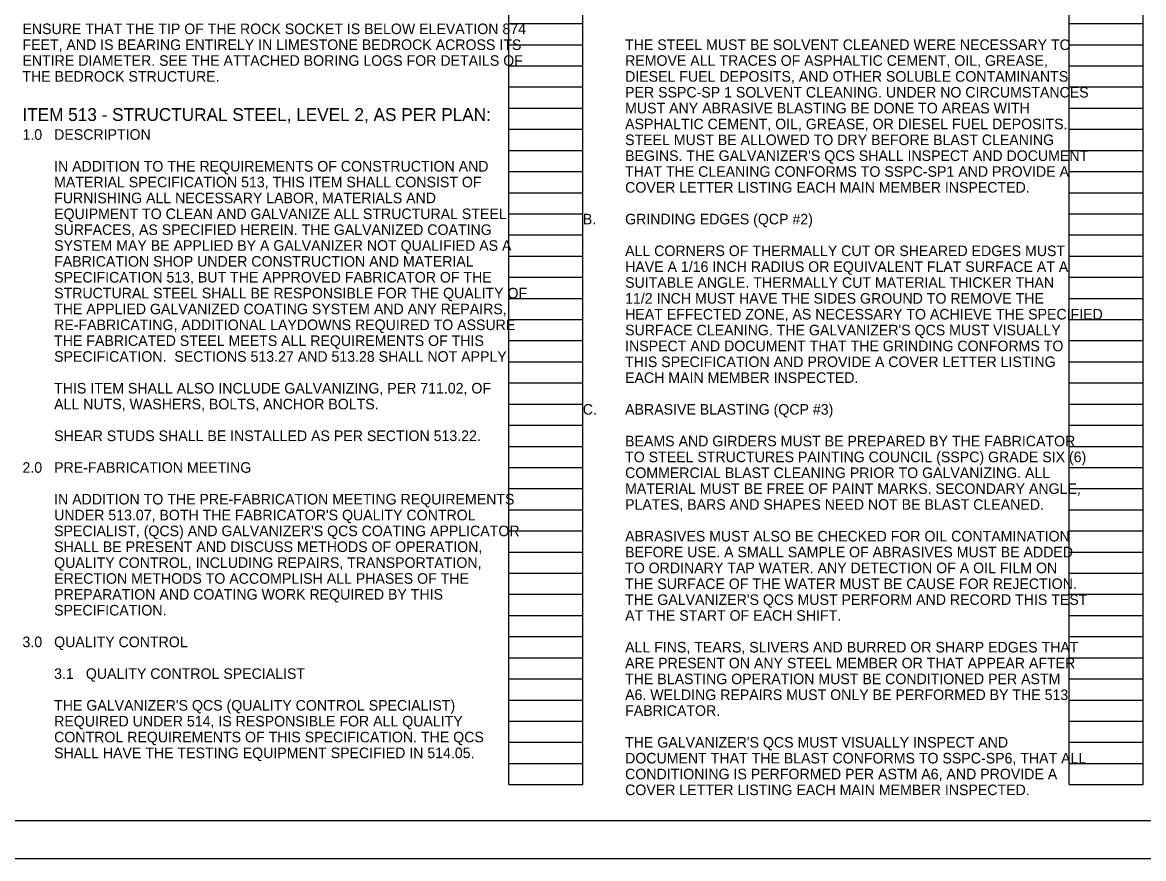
# Model space of a CAD drawing. Extents: x 0 to 45.3, y 0 to 22.
# Drawn here: x 9.82 to 24.66, y 0 to 11.07 of the extents above; entities that cross this region are included whole.
import ezdxf

# ---------------------------------------------------------------- set-up
doc = ezdxf.new("R2010")
doc.units = 0
for name, color, linetype in [('BR_P_Gen_Text', 7, 'Continuous'), ('SH_Border', 7, 'Continuous'), ('SH_Cut_Line', 7, 'Continuous'), ('SH_Data', 7, 'Continuous'), ('SH_Text', 7, 'Continuous')]:
    doc.layers.add(name, color=color, linetype=linetype)

msp = doc.modelspace()

# ---------------------------------------------------------------- linework, layer by layer
at = {"layer": 'SH_Border'}
msp.add_lwpolyline([(1.5, 21.5), (33.5, 21.5), (33.5, 0.5), (1.5, 0.5)], close=True, dxfattribs=at)
at = {"layer": 'SH_Cut_Line'}
msp.add_lwpolyline([(0, 0), (34, 0), (34, 22), (0, 22)], close=True, dxfattribs=at)
at = {"layer": 'SH_Data'}
for p, q in [((16.26, 0.98), (16.26, 21.14)), ((17.24, 0.98), (17.24, 21.14)), ((23.68, 0.98), (23.68, 21.14)), ((24.66, 0.98), (24.66, 21.14)), ((16.26, 11.06), (17.24, 11.06)), ((23.68, 11.06), (24.66, 11.06)), ((16.26, 10.78), (17.24, 10.78)), ((23.68, 10.78), (24.66, 10.78)), ((16.26, 10.5), (17.24, 10.5)), ((23.68, 10.5), (24.66, 10.5)), ((16.26, 10.22), (17.24, 10.22)), ((23.68, 10.22), (24.66, 10.22)), ((16.26, 9.94), (17.24, 9.94)), ((23.68, 9.94), (24.66, 9.94)), ((16.26, 9.66), (17.24, 9.66)), ((23.68, 9.66), (24.66, 9.66)), ((16.26, 9.38), (17.24, 9.38)), ((23.68, 9.38), (24.66, 9.38)), ((16.26, 9.1), (17.24, 9.1)), ((23.68, 9.1), (24.66, 9.1)), ((16.26, 8.82), (17.24, 8.82)), ((23.68, 8.82), (24.66, 8.82)), ((16.26, 8.54), (17.24, 8.54)), ((23.68, 8.54), (24.66, 8.54)), ((16.26, 8.26), (17.24, 8.26)), ((23.68, 8.26), (24.66, 8.26)), ((16.26, 7.98), (17.24, 7.98)), ((23.68, 7.98), (24.66, 7.98)), ((16.26, 7.7), (17.24, 7.7)), ((23.68, 7.7), (24.66, 7.7)), ((16.26, 7.42), (17.24, 7.42)), ((23.68, 7.42), (24.66, 7.42)), ((16.26, 7.14), (17.24, 7.14)), ((23.68, 7.14), (24.66, 7.14)), ((16.26, 6.86), (17.24, 6.86)), ((23.68, 6.86), (24.66, 6.86)), ((16.26, 6.58), (17.24, 6.58)), ((23.68, 6.58), (24.66, 6.58)), ((16.26, 6.3), (17.24, 6.3)), ((23.68, 6.3), (24.66, 6.3)), ((16.26, 6.02), (17.24, 6.02)), ((23.68, 6.02), (24.66, 6.02)), ((16.26, 5.74), (17.24, 5.74)), ((23.68, 5.74), (24.66, 5.74)), ((16.26, 5.46), (17.24, 5.46)), ((23.68, 5.46), (24.66, 5.46)), ((16.26, 5.18), (17.24, 5.18)), ((23.68, 5.18), (24.66, 5.18)), ((16.26, 4.9), (17.24, 4.9)), ((23.68, 4.9), (24.66, 4.9)), ((16.26, 4.62), (17.24, 4.62)), ((23.68, 4.62), (24.66, 4.62)), ((16.26, 4.34), (17.24, 4.34)), ((23.68, 4.34), (24.66, 4.34)), ((16.26, 4.06), (17.24, 4.06)), ((23.68, 4.06), (24.66, 4.06)), ((16.26, 3.78), (17.24, 3.78)), ((23.68, 3.78), (24.66, 3.78)), ((16.26, 3.5), (17.24, 3.5)), ((23.68, 3.5), (24.66, 3.5)), ((16.26, 3.22), (17.24, 3.22)), ((23.68, 3.22), (24.66, 3.22)), ((16.26, 2.94), (17.24, 2.94)), ((23.68, 2.94), (24.66, 2.94)), ((16.26, 2.66), (17.24, 2.66)), ((23.68, 2.66), (24.66, 2.66)), ((16.26, 2.38), (17.24, 2.38)), ((23.68, 2.38), (24.66, 2.38)), ((16.26, 2.1), (17.24, 2.1)), ((23.68, 2.1), (24.66, 2.1)), ((16.26, 1.82), (17.24, 1.82)), ((23.68, 1.82), (24.66, 1.82)), ((16.26, 1.54), (17.24, 1.54)), ((23.68, 1.54), (24.66, 1.54)), ((16.26, 1.26), (17.24, 1.26)), ((23.68, 1.26), (24.66, 1.26)), ((16.26, 0.98), (17.24, 0.98)), ((23.68, 0.98), (24.66, 0.98))]:
    msp.add_line(p, q, dxfattribs=at)

# ---------------------------------------------------------------- texts
at = {"layer": 'BR_P_Gen_Text'}
for s, height, p in [('THE STEEL MUST BE SOLVENT CLEANED WERE NECESSARY TO ', 0.14, (17.8, 10.71)), ('REMOVE ALL TRACES OF ASPHALTIC CEMENT, OIL, GREASE, ', 0.14, (17.8, 10.5)), ('DIESEL FUEL DEPOSITS, AND OTHER SOLUBLE CONTAMINANTS ', 0.14, (17.8, 10.29)), ('PER SSPC-SP 1 SOLVENT CLEANING. UNDER NO CIRCUMSTANCES ', 0.14, (17.8, 10.08)), ('MUST ANY ABRASIVE BLASTING BE DONE TO AREAS WITH ', 0.14, (17.8, 9.87)), ('ITEM 513 - STRUCTURAL STEEL, LEVEL 2, AS PER PLAN:', 0.17, (9.82, 9.77)), ('ASPHALTIC CEMENT, OIL, GREASE, OR DIESEL FUEL DEPOSITS. ', 0.14, (17.8, 9.66)), ('1.0', 0.14, (9.821, 9.52)), ('DESCRIPTION', 0.14, (10.24, 9.52)), ('STEEL MUST BE ALLOWED TO DRY BEFORE BLAST CLEANING ', 0.14, (17.8, 9.45)), ("BEGINS. THE GALVANIZER'S QCS SHALL INSPECT AND DOCUMENT ", 0.14, (17.8, 9.24)), ('IN ADDITION TO THE REQUIREMENTS OF CONSTRUCTION AND ', 0.14, (10.24, 9.1)), ('THAT THE CLEANING CONFORMS TO SSPC-SP1 AND PROVIDE A ', 0.14, (17.8, 9.03)), ('MATERIAL SPECIFICATION 513, THIS ITEM SHALL CONSIST OF ', 0.14, (10.24, 8.89)), ('COVER LETTER LISTING EACH MAIN MEMBER INSPECTED.', 0.14, (17.8, 8.82)), ('FURNISHING ALL NECESSARY LABOR, MATERIALS AND ', 0.14, (10.24, 8.68)), ('EQUIPMENT TO CLEAN AND GALVANIZE ALL STRUCTURAL STEEL ', 0.14, (10.24, 8.47)), ('B.', 0.14, (17.24, 8.4)), ('GRINDING EDGES (QCP #2)', 0.14, (17.8, 8.4)), ('SURFACES, AS SPECIFIED HEREIN. THE GALVANIZED COATING ', 0.14, (10.24, 8.26)), ('SYSTEM MAY BE APPLIED BY A GALVANIZER NOT QUALIFIED AS A ', 0.14, (10.24, 8.05)), ('ALL CORNERS OF THERMALLY CUT OR SHEARED EDGES MUST ', 0.14, (17.8, 7.98)), ('FABRICATION SHOP UNDER CONSTRUCTION AND MATERIAL ', 0.14, (10.24, 7.84)), ('HAVE A 1/16 INCH RADIUS OR EQUIVALENT FLAT SURFACE AT A ', 0.14, (17.8, 7.77)), ('SPECIFICATION 513, BUT THE APPROVED FABRICATOR OF THE ', 0.14, (10.24, 7.63)), ('SUITABLE ANGLE. THERMALLY CUT MATERIAL THICKER THAN ', 0.14, (17.8, 7.56)), ('STRUCTURAL STEEL SHALL BE RESPONSIBLE FOR THE QUALITY OF ', 0.14, (10.24, 7.42)), ('11/2 INCH MUST HAVE THE SIDES GROUND TO REMOVE THE ', 0.14, (17.8, 7.35)), ('THE APPLIED GALVANIZED COATING SYSTEM AND ANY REPAIRS, ', 0.14, (10.24, 7.21)), ('HEAT EFFECTED ZONE, AS NECESSARY TO ACHIEVE THE SPECIFIED ', 0.14, (17.8, 7.14)), ('RE-FABRICATING, ADDITIONAL LAYDOWNS REQUIRED TO ASSURE ', 0.14, (10.24, 7)), ("SURFACE CLEANING. THE GALVANIZER'S QCS MUST VISUALLY ", 0.14, (17.8, 6.93)), ('THE FABRICATED STEEL MEETS ALL REQUIREMENTS OF THIS ', 0.14, (10.24, 6.79)), ('INSPECT AND DOCUMENT THAT THE GRINDING CONFORMS TO ', 0.14, (17.8, 6.72)), ('SPECIFICATION.  SECTIONS 513.27 AND 513.28 SHALL NOT APPLY.', 0.14, (10.24, 6.58)), ('THIS SPECIFICATION AND PROVIDE A COVER LETTER LISTING ', 0.14, (17.8, 6.51)), ('EACH MAIN MEMBER INSPECTED.', 0.14, (17.8, 6.3)), ('THIS ITEM SHALL ALSO INCLUDE GALVANIZING, PER 711.02, OF ', 0.14, (10.24, 6.16)), ('ALL NUTS, WASHERS, BOLTS, ANCHOR BOLTS.', 0.14, (10.24, 5.95)), ('C.', 0.14, (17.24, 5.88)), ('ABRASIVE BLASTING (QCP #3)', 0.14, (17.8, 5.88)), ('SHEAR STUDS SHALL BE INSTALLED AS PER SECTION 513.22. ', 0.14, (10.24, 5.53)), ('BEAMS AND GIRDERS MUST BE PREPARED BY THE FABRICATOR ', 0.14, (17.8, 5.46)), ('TO STEEL STRUCTURES PAINTING COUNCIL (SSPC) GRADE SIX (6) ', 0.14, (17.8, 5.25)), ('2.0 ', 0.14, (9.821, 5.11)), ('PRE-FABRICATION MEETING ', 0.14, (10.24, 5.11)), ('COMMERCIAL BLAST CLEANING PRIOR TO GALVANIZING. ALL ', 0.14, (17.8, 5.04)), ('MATERIAL MUST BE FREE OF PAINT MARKS. SECONDARY ANGLE, ', 0.14, (17.8, 4.83)), ('IN ADDITION TO THE PRE-FABRICATION MEETING REQUIREMENTS ', 0.14, (10.24, 4.69)), ('PLATES, BARS AND SHAPES NEED NOT BE BLAST CLEANED.', 0.14, (17.8, 4.62)), ("UNDER 513.07, BOTH THE FABRICATOR'S QUALITY CONTROL ", 0.14, (10.24, 4.48)), ("SPECIALIST, (QCS) AND GALVANIZER'S QCS COATING APPLICATOR ", 0.14, (10.24, 4.27)), ('ABRASIVES MUST ALSO BE CHECKED FOR OIL CONTAMINATION ', 0.14, (17.8, 4.2)), ('SHALL BE PRESENT AND DISCUSS METHODS OF OPERATION, ', 0.14, (10.24, 4.06)), ('BEFORE USE. A SMALL SAMPLE OF ABRASIVES MUST BE ADDED ', 0.14, (17.8, 3.99)), ('QUALITY CONTROL, INCLUDING REPAIRS, TRANSPORTATION, ', 0.14, (10.24, 3.85)), ('TO ORDINARY TAP WATER. ANY DETECTION OF A OIL FILM ON ', 0.14, (17.8, 3.78)), ('ERECTION METHODS TO ACCOMPLISH ALL PHASES OF THE ', 0.14, (10.24, 3.64)), ('THE SURFACE OF THE WATER MUST BE CAUSE FOR REJECTION. ', 0.14, (17.8, 3.57)), ('PREPARATION AND COATING WORK REQUIRED BY THIS ', 0.14, (10.24, 3.43)), ("THE GALVANIZER'S QCS MUST PERFORM AND RECORD THIS TEST ", 0.14, (17.8, 3.36)), ('SPECIFICATION. ', 0.14, (10.24, 3.22)), ('AT THE START OF EACH SHIFT. ', 0.14, (17.8, 3.15)), ('3.0', 0.14, (9.821, 2.8)), ('QUALITY CONTROL ', 0.14, (10.24, 2.8)), ('ALL FINS, TEARS, SLIVERS AND BURRED OR SHARP EDGES THAT ', 0.14, (17.8, 2.73)), ('ARE PRESENT ON ANY STEEL MEMBER OR THAT APPEAR AFTER ', 0.14, (17.8, 2.52)), ('3.1 ', 0.14, (10.24, 2.38)), ('QUALITY CONTROL SPECIALIST ', 0.14, (10.66, 2.38)), ('THE BLASTING OPERATION MUST BE CONDITIONED PER ASTM ', 0.14, (17.8, 2.31)), ('A6. WELDING REPAIRS MUST ONLY BE PERFORMED BY THE 513 ', 0.14, (17.8, 2.1)), ("THE GALVANIZER'S QCS (QUALITY CONTROL SPECIALIST) ", 0.14, (10.24, 1.96)), ('FABRICATOR.', 0.14, (17.8, 1.89)), ('REQUIRED UNDER 514, IS RESPONSIBLE FOR ALL QUALITY ', 0.14, (10.24, 1.75)), ('CONTROL REQUIREMENTS OF THIS SPECIFICATION. THE QCS ', 0.14, (10.24, 1.54)), ("THE GALVANIZER'S QCS MUST VISUALLY INSPECT AND ", 0.14, (17.8, 1.47)), ('SHALL HAVE THE TESTING EQUIPMENT SPECIFIED IN 514.05.', 0.14, (10.24, 1.33)), ('DOCUMENT THAT THE BLAST CONFORMS TO SSPC-SP6, THAT ALL ', 0.14, (17.8, 1.26)), ('CONDITIONING IS PERFORMED PER ASTM A6, AND PROVIDE A ', 0.14, (17.8, 1.05)), ('COVER LETTER LISTING EACH MAIN MEMBER INSPECTED.', 0.14, (17.8, 0.84))]:
    msp.add_text(s, height=height, dxfattribs=at).set_placement(p)
at = {"layer": 'SH_Text'}
for s, p in [('ENSURE THAT THE TIP OF THE ROCK SOCKET IS BELOW ELEVATION 874 ', (9.82, 10.92)), ('FEET, AND IS BEARING ENTIRELY IN LIMESTONE BEDROCK ACROSS ITS ', (9.82, 10.71)), ('ENTIRE DIAMETER. SEE THE ATTACHED BORING LOGS FOR DETAILS OF ', (9.82, 10.5)), ('THE BEDROCK STRUCTURE.', (9.82, 10.29))]:
    msp.add_text(s, height=0.14, dxfattribs=at).set_placement(p)

doc.saveas('drawing.dxf')
